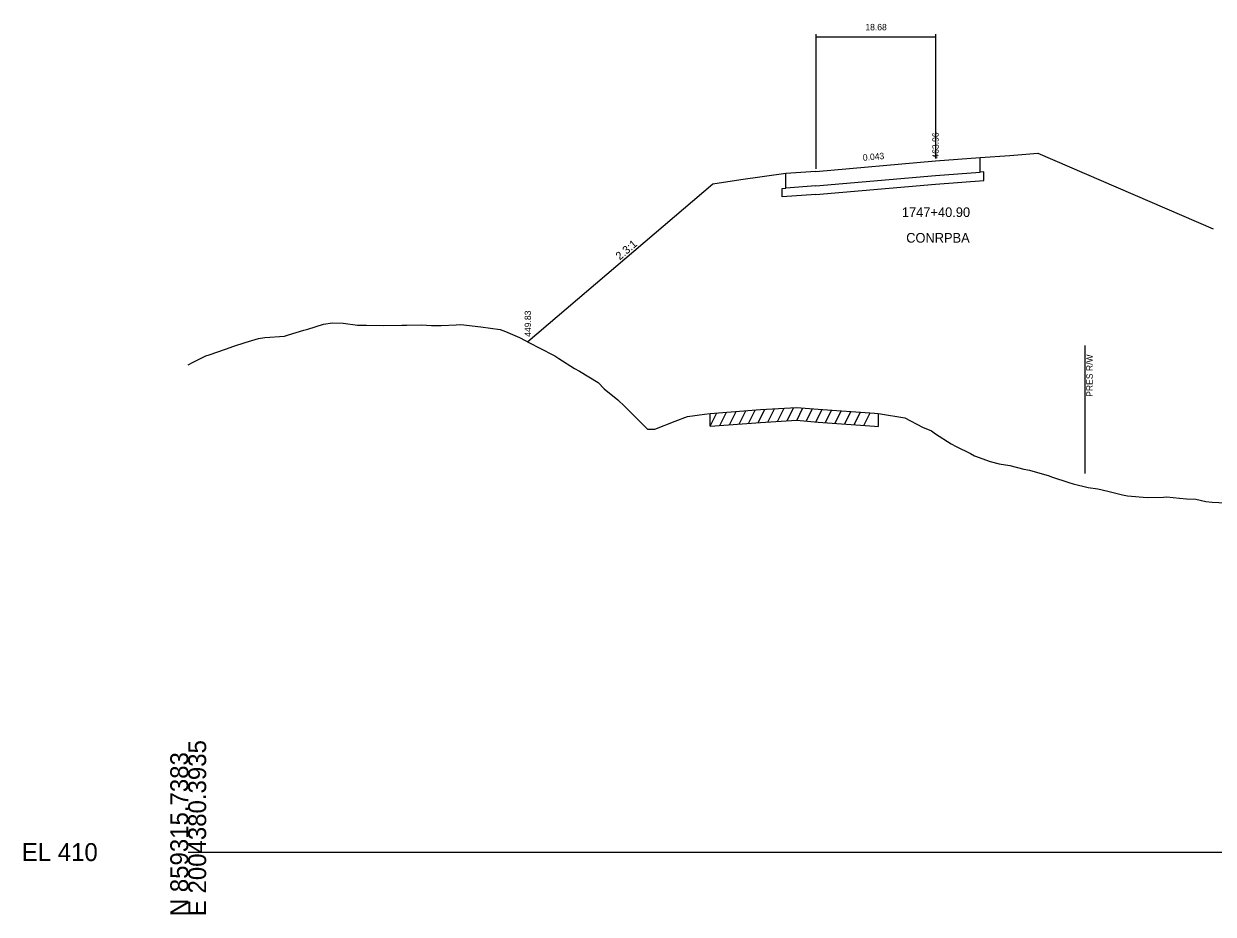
# Model space of a CAD drawing. Extents: x 2004049 to 2067449, y 841632 to 859611.
# Drawn here: x 2060920.8 to 2061106.6, y 847203.8 to 847342.9 of the extents above; entities that cross this region are included whole.
import ezdxf

# ---------------------------------------------------------------- set-up
doc = ezdxf.new("R2010")
doc.units = 0
for name, color, linetype in [('RD_GPK_XS_Cell', 7, 'Continuous'), ('RD_PD_NON-PLOTTING', 7, 'Continuous'), ('RD_XS_ExGround', 7, 'Continuous'), ('RD_XS_ExPaveRet', 7, 'Continuous'), ('RD_XS_TX_Box', 7, 'Continuous')]:
    doc.layers.add(name, color=color, linetype=linetype)

msp = doc.modelspace()

# ---------------------------------------------------------------- linework, layer by layer
at = {"layer": 'RD_GPK_XS_Cell'}
msp.add_line((2060946.51, 847213.53), (2061196.51, 847213.53), dxfattribs=at)
at = {"layer": 'RD_PD_NON-PLOTTING'}
for p, q in [((2061044.57, 847341.24), (2061044.57, 847320.22)), ((2061044.57, 847340.84), (2061063.25, 847340.84)), ((2061063.25, 847341.24), (2061063.25, 847321.84)), ((2061044.57, 847319.82), (2061063.25, 847321.44)), ((2061063.25, 847321.44), (2061070.23, 847321.96)), ((2061070.23, 847321.96), (2061074.88, 847322.31)), ((2061070.23, 847319.7), (2061070.23, 847321.96)), ((2061074.88, 847322.31), (2061079.24, 847322.64)), ((2061079.24, 847322.64), (2061106.63, 847310.86)), ((2061039.88, 847319.47), (2061032.85, 847318.47)), ((2061044.57, 847319.82), (2061039.88, 847319.47)), ((2061039.88, 847317.2), (2061039.88, 847319.47)), ((2061044.57, 847317.55), (2061063.25, 847319.18)), ((2061063.25, 847319.18), (2061070.23, 847319.7)), ((2061070.81, 847319.74), (2061070.23, 847319.7)), ((2061070.81, 847318.41), (2061070.81, 847319.74)), ((2061028.45, 847317.84), (2060999.56, 847293.19)), ((2061032.85, 847318.47), (2061028.45, 847317.84)), ((2061044.57, 847317.55), (2061039.88, 847317.2)), ((2061044.57, 847316.22), (2061063.25, 847317.84)), ((2061063.25, 847317.84), (2061070.81, 847318.41)), ((2061039.29, 847317.16), (2061039.88, 847317.2)), ((2061039.29, 847315.83), (2061039.29, 847317.16)), ((2061044.57, 847316.22), (2061039.29, 847315.83))]:
    msp.add_line(p, q, dxfattribs=at)
at = {"layer": 'RD_XS_ExGround'}
msp.add_lwpolyline([(2060946.51, 847289.63), (2060947.26, 847290.01), (2060949.27, 847291.03), (2060949.79, 847291.16), (2060952.34, 847292.04), (2060953.65, 847292.52), (2060955.4, 847293.12), (2060957.51, 847293.72), (2060958.46, 847293.9), (2060961.53, 847294.07), (2060962.16, 847294.27), (2060964.59, 847295), (2060965.22, 847295.2), (2060967.65, 847295.96), (2060969.07, 847296.16), (2060970.72, 847296.13), (2060972.93, 847295.82), (2060973.78, 847295.78), (2060974.34, 847295.78), (2060977.06, 847295.76), (2060979.9, 847295.79), (2060980.64, 847295.82), (2060982.97, 847295.86), (2060984.5, 847295.76), (2060986.03, 847295.76), (2060988.35, 847295.86), (2060989.09, 847295.91), (2060992.21, 847295.56), (2060995.22, 847295.15), (2060996.06, 847294.81), (2060998.28, 847293.86), (2060999.92, 847293), (2061001.35, 847292.26), (2061003.78, 847291.02), (2061004.41, 847290.62), (2061006.87, 847289.05), (2061007.63, 847288.61), (2061010.54, 847286.84), (2061011.49, 847285.87), (2061013.6, 847284.12), (2061014.72, 847283.08), (2061018.28, 847279.59), (2061018.75, 847279.58), (2061019.4, 847279.56), (2061022.6, 847280.81), (2061024.51, 847281.55), (2061027.14, 847281.9), (2061028.06, 847282.03), (2061035.93, 847282.61), (2061041.51, 847282.95), (2061044.9, 847282.68), (2061053.7, 847282.04), (2061054.31, 847281.99), (2061054.64, 847281.94), (2061058.44, 847281.32), (2061061.2, 847279.89), (2061062.61, 847279.28), (2061063.27, 847278.85), (2061065.68, 847277.29), (2061066.48, 847276.84), (2061068.74, 847275.78), (2061069.33, 847275.39), (2061071.8, 847274.53), (2061073.18, 847274.14), (2061074.87, 847273.87), (2061077.04, 847273.34), (2061077.93, 847273.15), (2061080.99, 847272.29), (2061081.38, 847272.14), (2061084.06, 847271.24), (2061084.75, 847271.05), (2061087.12, 847270.48), (2061088.61, 847270.23), (2061090.18, 847269.89), (2061092.46, 847269.31), (2061093.25, 847269.15), (2061096.31, 847268.87), (2061098.85, 847268.95), (2061099.37, 847268.99), (2061101.39, 847268.79), (2061102.44, 847268.69), (2061103.93, 847268.61), (2061105.5, 847268.26), (2061106.47, 847268.19), (2061108.56, 847268.05)], dxfattribs=at)
at = {"layer": 'RD_XS_ExPaveRet'}
for p, q in [((2061028.06, 847280.03), (2061029.1, 847282.11)), ((2061028.06, 847280.03), (2061028.06, 847282.03)), ((2061029.56, 847280.14), (2061030.6, 847282.22)), ((2061031.06, 847280.25), (2061032.1, 847282.33)), ((2061032.56, 847280.36), (2061033.6, 847282.44)), ((2061034.06, 847280.47), (2061035.1, 847282.55)), ((2061035.56, 847280.58), (2061036.59, 847282.65)), ((2061037.06, 847280.68), (2061038.09, 847282.74)), ((2061038.56, 847280.77), (2061039.59, 847282.83)), ((2061040.06, 847280.86), (2061041.09, 847282.92)), ((2061041.56, 847280.94), (2061042.52, 847282.87)), ((2061043.06, 847280.82), (2061044.02, 847282.75)), ((2061044.56, 847280.71), (2061045.52, 847282.63)), ((2061046.06, 847280.6), (2061047.02, 847282.52)), ((2061047.56, 847280.49), (2061048.52, 847282.41)), ((2061049.06, 847280.38), (2061050.02, 847282.31)), ((2061050.56, 847280.27), (2061051.52, 847282.2)), ((2061052.06, 847280.16), (2061053.02, 847282.09)), ((2061054.31, 847281.99), (2061054.31, 847279.99)), ((2061028.06, 847280.03), (2061035.93, 847280.61)), ((2061035.93, 847280.61), (2061041.51, 847280.95)), ((2061041.51, 847280.95), (2061044.9, 847280.68)), ((2061044.9, 847280.68), (2061053.7, 847280.04)), ((2061053.7, 847280.04), (2061054.31, 847279.99))]:
    msp.add_line(p, q, dxfattribs=at)
at = {"layer": 'RD_XS_TX_Box'}
msp.add_line((2061086.56, 847292.62), (2061086.56, 847272.62), dxfattribs=at)

# ---------------------------------------------------------------- texts
at = {"layer": 'RD_GPK_XS_Cell'}
for s, p in [('E 2004380.3935', (2060949.31, 847203.53)), ('N 859315.7383', (2060946.51, 847203.53))]:
    msp.add_text(s, height=2.8, rotation=90, dxfattribs=at).set_placement(p)
msp.add_text('EL 410', height=2.8, dxfattribs=at).set_placement((2060920.51, 847212.13))
at = {"layer": 'RD_PD_NON-PLOTTING'}
for s, height, p in [('18.68', 1, (2061052.29, 847341.84)), ('1747+40.90', 1.5, (2061058, 847312.69)), ('CONRPBA', 1.5, (2061058.67, 847308.69))]:
    msp.add_text(s, height=height, dxfattribs=at).set_placement(p)
for s, height, rotation, p in [(' 463.96', 1, 90, (2061063.75, 847321.44)), ('0.043', 1, 4.9711, (2061051.94, 847321.46)), ('2.3:1', 1.25, 40.4719, (2061013.93, 847305.89)), ('449.83', 1, 90, (2061000.06, 847293.99))]:
    msp.add_text(s, height=height, rotation=rotation, dxfattribs=at).set_placement(p)
at = {"layer": 'RD_XS_TX_Box'}
msp.add_text('PRES R/W', height=1, rotation=90, dxfattribs=at).set_placement((2061087.81, 847284.62))

doc.saveas('drawing.dxf')
